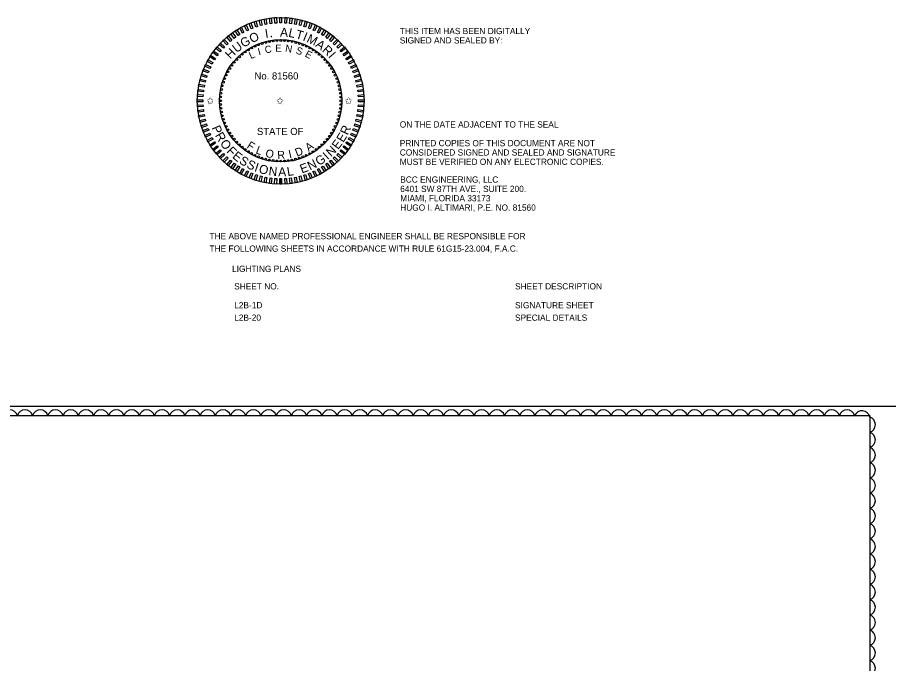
# Model space of a CAD drawing. Extents: x -816.9 to -790.1, y -2199.5 to -2184.5.
# Drawn here: x -804.97 to -795.17, y -2191.79 to -2184.53 of the extents above; entities that cross this region are included whole.
import ezdxf

# ---------------------------------------------------------------- set-up
doc = ezdxf.new("R2010")
doc.units = 0
for name, color, linetype in [('Cloud_dp', 7, 'Continuous'), ('Logo_dp', 7, 'Continuous'), ('NonPlottingEle_dp', 7, 'Continuous'), ('PlotBorder_dp', 7, 'Continuous'), ('SheetBorder_dp', 7, 'Continuous'), ('TextMisc', 7, 'Continuous'), ('TextNotes', 7, 'Continuous')]:
    doc.layers.add(name, color=color, linetype=linetype)

msp = doc.modelspace()

# ---------------------------------------------------------------- linework, layer by layer
at = {"layer": 'Cloud_dp'}
for centre, radius, start, end in [((-805.0532, -2189.0276), 0.0897, 17.5, 162.5), ((-804.882, -2189.0276), 0.0897, 17.5, 162.5), ((-804.7109, -2189.0276), 0.0897, 17.5, 162.5), ((-804.5398, -2189.0276), 0.0897, 17.5, 162.5), ((-804.3687, -2189.0276), 0.0897, 17.5, 162.5), ((-804.1976, -2189.0276), 0.0897, 17.5, 162.5), ((-804.0264, -2189.0276), 0.0897, 17.5, 162.5), ((-803.8553, -2189.0276), 0.0897, 17.5, 162.5), ((-803.6842, -2189.0276), 0.0897, 17.5, 162.5), ((-803.5131, -2189.0276), 0.0897, 17.5, 162.5), ((-803.3419, -2189.0276), 0.0897, 17.5, 162.5), ((-803.1708, -2189.0276), 0.0897, 17.5, 162.5), ((-802.9997, -2189.0276), 0.0897, 17.5, 162.5), ((-802.8286, -2189.0276), 0.0897, 17.5, 162.5), ((-802.6575, -2189.0276), 0.0897, 17.5, 162.5), ((-802.4863, -2189.0276), 0.0897, 17.5, 162.5), ((-802.3152, -2189.0276), 0.0897, 17.5, 162.5), ((-802.1441, -2189.0276), 0.0897, 17.5, 162.5), ((-801.973, -2189.0276), 0.0897, 17.5, 162.5), ((-801.8018, -2189.0276), 0.0897, 17.5, 162.5), ((-801.6307, -2189.0276), 0.0897, 17.5, 162.5), ((-801.4596, -2189.0276), 0.0897, 17.5, 162.5), ((-801.2885, -2189.0276), 0.0897, 17.5, 162.5), ((-801.1174, -2189.0276), 0.0897, 17.5, 162.5), ((-800.9462, -2189.0276), 0.0897, 17.5, 162.5), ((-800.7751, -2189.0276), 0.0897, 17.5, 162.5), ((-800.604, -2189.0276), 0.0897, 17.5, 162.5), ((-800.4329, -2189.0276), 0.0897, 17.5, 162.5), ((-800.2617, -2189.0276), 0.0897, 17.5, 162.5), ((-800.0906, -2189.0276), 0.0897, 17.5, 162.5), ((-799.9195, -2189.0276), 0.0897, 17.5, 162.5), ((-799.7484, -2189.0276), 0.0897, 17.5, 162.5), ((-799.5772, -2189.0276), 0.0897, 17.5, 162.5), ((-799.4061, -2189.0276), 0.0897, 17.5, 162.5), ((-799.235, -2189.0276), 0.0897, 17.5, 162.5), ((-799.0639, -2189.0276), 0.0897, 17.5, 162.5), ((-798.8928, -2189.0276), 0.0897, 17.5, 162.5), ((-798.7216, -2189.0276), 0.0897, 17.5, 162.5), ((-798.5505, -2189.0276), 0.0897, 17.5, 162.5), ((-798.3794, -2189.0276), 0.0897, 17.5, 162.5), ((-798.2083, -2189.0276), 0.0897, 17.5, 162.5), ((-798.0371, -2189.0276), 0.0897, 17.5, 162.5), ((-797.866, -2189.0276), 0.0897, 17.5, 162.5), ((-797.6949, -2189.0276), 0.0897, 17.5, 162.5), ((-797.5238, -2189.0276), 0.0897, 17.5, 162.5), ((-797.3527, -2189.0276), 0.0897, 17.5, 162.5), ((-797.1815, -2189.0276), 0.0897, 17.5, 162.5), ((-797.0104, -2189.0276), 0.0897, 17.5, 162.5), ((-796.8393, -2189.0276), 0.0897, 17.5, 162.5), ((-796.6682, -2189.0276), 0.0897, 17.5, 162.5), ((-796.497, -2189.0276), 0.0897, 17.5, 162.5), ((-796.3259, -2189.0276), 0.0897, 17.5, 162.5), ((-796.1548, -2189.0276), 0.0897, 17.5, 162.5), ((-795.9837, -2189.0276), 0.0897, 17.5, 162.5), ((-795.8126, -2189.0276), 0.0897, 17.5, 162.5), ((-795.6414, -2189.0276), 0.0897, 17.5, 162.5), ((-795.4735, -2189.036), 0.0896, 11.74536, 156.74536), ((-795.4127, -2189.1033), 0.0897, 287.5, 72.5), ((-795.4127, -2189.2745), 0.0897, 287.5, 72.5), ((-795.4127, -2189.4456), 0.0897, 287.5, 72.5), ((-795.4127, -2189.6167), 0.0897, 287.5, 72.5), ((-795.4127, -2189.7878), 0.0897, 287.5, 72.5), ((-795.4127, -2189.959), 0.0897, 287.5, 72.5), ((-795.4127, -2190.1301), 0.0897, 287.5, 72.5), ((-795.4127, -2190.3012), 0.0897, 287.5, 72.5), ((-795.4127, -2190.4723), 0.0897, 287.5, 72.5), ((-795.4127, -2190.6434), 0.0897, 287.5, 72.5), ((-795.4127, -2190.8146), 0.0897, 287.5, 72.5), ((-795.4127, -2190.9857), 0.0897, 287.5, 72.5), ((-795.4127, -2191.1568), 0.0897, 287.5, 72.5), ((-795.4127, -2191.3279), 0.0897, 287.5, 72.5), ((-795.4127, -2191.4991), 0.0897, 287.5, 72.5), ((-795.4127, -2191.6702), 0.0897, 287.5, 72.5), ((-795.4127, -2191.8413), 0.0897, 287.5, 72.5)]:
    msp.add_arc(centre, radius, start, end, dxfattribs=at)
at = {"layer": 'Logo_dp'}
for p, q in [((-802.0181, -2186.4002), (-802.0183, -2186.3377)), ((-802.0081, -2186.4002), (-802.0083, -2186.3377)), ((-801.9981, -2186.4001), (-801.9983, -2186.3377))]:
    msp.add_line(p, q, dxfattribs=at)
for points in [[(-802.1076, -2184.594), (-802.1277, -2184.5965), (-802.1355, -2184.5346), (-802.1155, -2184.5321)], [(-802.0529, -2184.5894), (-802.073, -2184.5907), (-802.0769, -2184.5284), (-802.0568, -2184.5271)], [(-801.9979, -2184.5884), (-802.0181, -2184.5884), (-802.0181, -2184.5259), (-801.9979, -2184.5259)], [(-801.943, -2184.5907), (-801.9632, -2184.5895), (-801.9592, -2184.5272), (-801.9391, -2184.5284)], [(-801.8884, -2184.5965), (-801.9084, -2184.594), (-801.9006, -2184.5321), (-801.8806, -2184.5346)], [(-802.3713, -2184.6673), (-802.3896, -2184.6759), (-802.4161, -2184.6194), (-802.3979, -2184.6108)], [(-802.3206, -2184.646), (-802.3394, -2184.6535), (-802.3624, -2184.5954), (-802.3436, -2184.588)], [(-802.2687, -2184.628), (-802.2879, -2184.6343), (-802.3072, -2184.5749), (-802.288, -2184.5687)], [(-802.2158, -2184.6133), (-802.2353, -2184.6183), (-802.2508, -2184.5579), (-802.2313, -2184.5528)], [(-802.162, -2184.6019), (-802.1818, -2184.6057), (-802.1935, -2184.5444), (-802.1737, -2184.5406)], [(-801.8342, -2184.6058), (-801.854, -2184.602), (-801.8423, -2184.5407), (-801.8225, -2184.5444)], [(-801.7807, -2184.6184), (-801.8003, -2184.6133), (-801.7847, -2184.5529), (-801.7652, -2184.5579)], [(-801.7281, -2184.6343), (-801.7473, -2184.6281), (-801.728, -2184.5687), (-801.7088, -2184.5749)], [(-801.6766, -2184.6535), (-801.6954, -2184.6461), (-801.6724, -2184.5881), (-801.6537, -2184.5955)], [(-801.6265, -2184.6759), (-801.6447, -2184.6673), (-801.6182, -2184.6109), (-801.5999, -2184.6195)], [(-802.514, -2184.7494), (-802.5303, -2184.7613), (-802.567, -2184.7108), (-802.5507, -2184.6989)], [(-802.4682, -2184.7191), (-802.4852, -2184.7299), (-802.5187, -2184.6772), (-802.5016, -2184.6664)], [(-802.4206, -2184.6916), (-802.4382, -2184.7014), (-802.4683, -2184.6467), (-802.4506, -2184.6369)], [(-801.5778, -2184.7014), (-801.5955, -2184.6917), (-801.5654, -2184.637), (-801.5477, -2184.6468)], [(-801.5308, -2184.73), (-801.5479, -2184.7192), (-801.5144, -2184.6665), (-801.4974, -2184.6773)], [(-801.4857, -2184.7614), (-801.5021, -2184.7495), (-801.4654, -2184.699), (-801.4491, -2184.7109)], [(-802.6388, -2184.8569), (-802.6526, -2184.8716), (-802.6981, -2184.8288), (-802.6843, -2184.8141)], [(-802.5994, -2184.8184), (-802.6142, -2184.8323), (-802.6569, -2184.7868), (-802.6422, -2184.7729)], [(-802.5578, -2184.7826), (-802.5734, -2184.7955), (-802.6131, -2184.7474), (-802.5976, -2184.7345)], [(-801.4427, -2184.7956), (-801.4583, -2184.7827), (-801.4185, -2184.7346), (-801.4029, -2184.7475)], [(-801.4019, -2184.8324), (-801.4166, -2184.8186), (-801.3739, -2184.7731), (-801.3592, -2184.7869)], [(-801.3635, -2184.8717), (-801.3773, -2184.857), (-801.3318, -2184.8143), (-801.318, -2184.829)], [(-802.7098, -2184.9407), (-802.7216, -2184.957), (-802.7721, -2184.9203), (-802.7602, -2184.904)], [(-802.6756, -2184.8976), (-802.6884, -2184.9132), (-802.7365, -2184.8734), (-802.7237, -2184.8579)], [(-801.3277, -2184.9133), (-801.3405, -2184.8978), (-801.2924, -2184.858), (-801.2796, -2184.8736)], [(-801.2945, -2184.9571), (-801.3064, -2184.9408), (-801.2559, -2184.9041), (-801.244, -2184.9205)], [(-802.7697, -2185.0327), (-802.7794, -2185.0504), (-802.8341, -2185.0203), (-802.8244, -2185.0027)], [(-802.7412, -2184.9858), (-802.752, -2185.0028), (-802.8047, -2184.9694), (-802.7939, -2184.9523)], [(-801.2641, -2185.003), (-801.2749, -2184.9859), (-801.2222, -2184.9525), (-801.2114, -2184.9695)], [(-801.2367, -2185.0506), (-801.2464, -2185.0329), (-801.1917, -2185.0028), (-801.182, -2185.0205)], [(-802.8176, -2185.1316), (-802.825, -2185.1503), (-802.8831, -2185.1274), (-802.8756, -2185.1086)], [(-802.7952, -2185.0814), (-802.8038, -2185.0997), (-802.8603, -2185.0731), (-802.8517, -2185.0548)], [(-801.2123, -2185.0998), (-801.2209, -2185.0816), (-801.1645, -2185.055), (-801.1559, -2185.0732)], [(-801.1911, -2185.1505), (-801.1985, -2185.1317), (-801.1405, -2185.1088), (-801.1331, -2185.1275)], [(-802.8368, -2185.1831), (-802.8431, -2185.2022), (-802.9024, -2185.183), (-802.8962, -2185.1638)], [(-801.1731, -2185.2024), (-801.1793, -2185.1832), (-801.12, -2185.1639), (-801.1137, -2185.1831)], [(-802.8654, -2185.2891), (-802.8692, -2185.309), (-802.9305, -2185.2973), (-802.9267, -2185.2774)], [(-802.8528, -2185.2356), (-802.8578, -2185.2552), (-802.9182, -2185.2397), (-802.9132, -2185.2201)], [(-801.1584, -2185.2554), (-801.1634, -2185.2358), (-801.1029, -2185.2203), (-801.0979, -2185.2398)], [(-801.147, -2185.3091), (-801.1508, -2185.2893), (-801.0895, -2185.2776), (-801.0857, -2185.2974)], [(-802.8804, -2185.3979), (-802.8817, -2185.4181), (-802.944, -2185.4142), (-802.9427, -2185.394)], [(-802.8746, -2185.3433), (-802.8771, -2185.3633), (-802.9391, -2185.3555), (-802.9365, -2185.3355)], [(-801.139, -2185.3635), (-801.1416, -2185.3435), (-801.0797, -2185.3357), (-801.0771, -2185.3557)], [(-801.1345, -2185.4183), (-801.1358, -2185.3981), (-801.0735, -2185.3942), (-801.0722, -2185.4144)], [(-802.8828, -2185.4529), (-802.8828, -2185.473), (-802.9452, -2185.473), (-802.9452, -2185.4529)], [(-802.8817, -2185.5078), (-802.8804, -2185.5279), (-802.9427, -2185.5318), (-802.944, -2185.5117)], [(-801.1358, -2185.5281), (-801.1345, -2185.508), (-801.0722, -2185.5119), (-801.0735, -2185.532)], [(-801.1334, -2185.4732), (-801.1334, -2185.453), (-801.071, -2185.453), (-801.071, -2185.4732)], [(-802.8772, -2185.5626), (-802.8746, -2185.5826), (-802.9366, -2185.5904), (-802.9391, -2185.5704)], [(-801.1416, -2185.5828), (-801.1391, -2185.5627), (-801.0771, -2185.5706), (-801.0797, -2185.5906)], [(-802.8692, -2185.6169), (-802.8654, -2185.6368), (-802.9267, -2185.6484), (-802.9305, -2185.6286)], [(-802.8578, -2185.6707), (-802.8528, -2185.6902), (-802.9133, -2185.7058), (-802.9183, -2185.6862)], [(-801.1634, -2185.6904), (-801.1584, -2185.6709), (-801.098, -2185.6864), (-801.103, -2185.7059)], [(-801.1508, -2185.6369), (-801.147, -2185.6171), (-801.0857, -2185.6288), (-801.0895, -2185.6486)], [(-802.8431, -2185.7236), (-802.8369, -2185.7428), (-802.8962, -2185.7621), (-802.9025, -2185.7429)], [(-802.8251, -2185.7756), (-802.8177, -2185.7943), (-802.8757, -2185.8173), (-802.8831, -2185.7985)], [(-801.1986, -2185.7945), (-801.1912, -2185.7757), (-801.1331, -2185.7987), (-801.1406, -2185.8175)], [(-801.1794, -2185.743), (-801.1731, -2185.7238), (-801.1138, -2185.7431), (-801.12, -2185.7623)], [(-802.8039, -2185.8262), (-802.7953, -2185.8445), (-802.8518, -2185.8711), (-802.8604, -2185.8528)], [(-802.7795, -2185.8755), (-802.7698, -2185.8932), (-802.8245, -2185.9232), (-802.8342, -2185.9056)], [(-801.2465, -2185.8933), (-801.2368, -2185.8757), (-801.1821, -2185.9057), (-801.1918, -2185.9234)], [(-801.221, -2185.8447), (-801.2124, -2185.8264), (-801.1559, -2185.853), (-801.1645, -2185.8712)], [(-802.7521, -2185.9231), (-802.7413, -2185.9401), (-802.794, -2185.9736), (-802.8048, -2185.9566)], [(-802.7217, -2185.9689), (-802.7099, -2185.9852), (-802.7604, -2186.0219), (-802.7722, -2186.0056)], [(-801.3065, -2185.9854), (-801.2946, -2185.9691), (-801.2441, -2186.0058), (-801.256, -2186.0221)], [(-801.275, -2185.9403), (-801.2642, -2185.9233), (-801.2115, -2185.9567), (-801.2223, -2185.9738)], [(-802.6886, -2186.0127), (-802.6757, -2186.0283), (-802.7238, -2186.0681), (-802.7366, -2186.0525)], [(-802.6527, -2186.0544), (-802.6389, -2186.0691), (-802.6844, -2186.1118), (-802.6982, -2186.0971)], [(-802.6143, -2186.0937), (-802.5996, -2186.1075), (-802.6423, -2186.153), (-802.657, -2186.1392)], [(-801.4168, -2186.1076), (-801.4021, -2186.0938), (-801.3593, -2186.1393), (-801.374, -2186.1531)], [(-801.3775, -2186.0692), (-801.3637, -2186.0545), (-801.3182, -2186.0972), (-801.332, -2186.1119)], [(-801.3406, -2186.0284), (-801.3278, -2186.0129), (-801.2797, -2186.0527), (-801.2926, -2186.0682)], [(-802.5735, -2186.1305), (-802.5579, -2186.1434), (-802.5977, -2186.1914), (-802.6133, -2186.1786)], [(-802.5305, -2186.1647), (-802.5141, -2186.1765), (-802.5508, -2186.227), (-802.5672, -2186.2152)], [(-802.4854, -2186.1961), (-802.4683, -2186.2069), (-802.5018, -2186.2596), (-802.5188, -2186.2488)], [(-801.548, -2186.207), (-801.531, -2186.1962), (-801.4975, -2186.2489), (-801.5146, -2186.2597)], [(-801.5022, -2186.1766), (-801.4859, -2186.1648), (-801.4492, -2186.2153), (-801.4655, -2186.2271)], [(-801.4584, -2186.1435), (-801.4429, -2186.1306), (-801.4031, -2186.1787), (-801.4186, -2186.1916)], [(-802.4384, -2186.2246), (-802.4207, -2186.2343), (-802.4508, -2186.289), (-802.4685, -2186.2793)], [(-802.3897, -2186.2501), (-802.3715, -2186.2587), (-802.3981, -2186.3152), (-802.4163, -2186.3066)], [(-802.3396, -2186.2725), (-802.3208, -2186.28), (-802.3438, -2186.338), (-802.3625, -2186.3306)], [(-802.2881, -2186.2918), (-802.2689, -2186.298), (-802.2882, -2186.3574), (-802.3074, -2186.3511)], [(-801.7475, -2186.298), (-801.7283, -2186.2918), (-801.709, -2186.3512), (-801.7282, -2186.3574)], [(-801.6956, -2186.28), (-801.6768, -2186.2726), (-801.6538, -2186.3306), (-801.6726, -2186.3381)], [(-801.6449, -2186.2588), (-801.6266, -2186.2502), (-801.6001, -2186.3067), (-801.6183, -2186.3153)], [(-801.5957, -2186.2344), (-801.578, -2186.2247), (-801.5479, -2186.2794), (-801.5656, -2186.2891)], [(-802.2355, -2186.3077), (-802.216, -2186.3127), (-802.2315, -2186.3732), (-802.251, -2186.3682)], [(-802.182, -2186.3203), (-802.1622, -2186.3241), (-802.1739, -2186.3854), (-802.1937, -2186.3816)], [(-802.1278, -2186.3295), (-802.1078, -2186.3321), (-802.1156, -2186.394), (-802.1357, -2186.3915)], [(-802.0732, -2186.3353), (-802.0531, -2186.3366), (-802.057, -2186.3989), (-802.0771, -2186.3976)], [(-802.0183, -2186.3377), (-801.9981, -2186.3377), (-801.9981, -2186.4001), (-802.0183, -2186.4001)], [(-801.9633, -2186.3366), (-801.9432, -2186.3354), (-801.9393, -2186.3977), (-801.9594, -2186.3989)], [(-801.9086, -2186.3321), (-801.8886, -2186.3296), (-801.8807, -2186.3915), (-801.9008, -2186.394)], [(-801.8542, -2186.3241), (-801.8344, -2186.3203), (-801.8227, -2186.3817), (-801.8425, -2186.3854)], [(-801.8004, -2186.3128), (-801.7809, -2186.3077), (-801.7654, -2186.3682), (-801.7849, -2186.3732)]]:
    msp.add_lwpolyline(points, close=True, dxfattribs=at)
for centre in [(-802.2569, -2184.8332), (-802.2168, -2184.8188), (-802.176, -2184.807), (-802.1344, -2184.7977), (-802.0924, -2184.7911), (-802.0501, -2184.7871), (-802.0075, -2184.7858), (-801.965, -2184.7872), (-801.9227, -2184.7912), (-801.8807, -2184.7979), (-801.8391, -2184.8073), (-801.7983, -2184.8192), (-801.7583, -2184.8336), (-802.4057, -2184.9148), (-802.3705, -2184.891), (-802.3339, -2184.8693), (-802.2959, -2184.85), (-801.7193, -2184.8505), (-801.6814, -2184.8699), (-801.6448, -2184.8916), (-801.6096, -2184.9155), (-802.5295, -2185.0309), (-802.5014, -2184.999), (-802.4713, -2184.969), (-802.4393, -2184.9409), (-801.576, -2184.9416), (-801.5441, -2184.9698), (-801.5141, -2184.9999), (-801.486, -2185.0318), (-802.5796, -2185.0997), (-802.5556, -2185.0645), (-801.4599, -2185.0654), (-801.436, -2185.1006), (-802.6375, -2185.2132), (-802.6206, -2185.1742), (-802.6013, -2185.1363), (-801.4144, -2185.1373), (-801.3951, -2185.1752), (-801.3783, -2185.2143), (-802.6639, -2185.2941), (-802.652, -2185.2532), (-801.3639, -2185.2543), (-801.352, -2185.2952), (-802.6839, -2185.4199), (-802.6799, -2185.3776), (-802.6732, -2185.3356), (-801.3428, -2185.3367), (-801.3362, -2185.3787), (-801.3322, -2185.4211), (-802.6853, -2185.4625), (-802.684, -2185.505), (-801.3323, -2185.5061), (-801.3309, -2185.4636), (-802.68, -2185.5473), (-802.6734, -2185.5894), (-801.343, -2185.5905), (-801.3363, -2185.5485), (-802.6642, -2185.6309), (-802.6523, -2185.6718), (-802.638, -2185.7118), (-801.3787, -2185.7128), (-801.3642, -2185.6728), (-801.3523, -2185.632), (-802.6211, -2185.7509), (-802.6018, -2185.7888), (-801.4149, -2185.7898), (-801.3956, -2185.7519), (-802.5802, -2185.8254), (-802.5563, -2185.8606), (-802.5303, -2185.8943), (-801.4867, -2185.8951), (-801.4606, -2185.8615), (-801.4366, -2185.8264), (-802.5021, -2185.9262), (-802.4721, -2185.9563), (-802.4402, -2185.9845), (-802.4066, -2186.0106), (-801.6105, -2186.0112), (-801.5769, -2185.9852), (-801.5449, -2185.9571), (-801.5148, -2185.927), (-802.3714, -2186.0345), (-802.3348, -2186.0562), (-802.297, -2186.0755), (-802.2579, -2186.0925), (-802.2179, -2186.1069), (-801.7994, -2186.1073), (-801.7593, -2186.0929), (-801.7203, -2186.076), (-801.6824, -2186.0567), (-801.6457, -2186.0351), (-802.1771, -2186.1188), (-802.1356, -2186.1281), (-802.0935, -2186.1348), (-802.0512, -2186.1389), (-802.0081, -2186.1403), (-801.9661, -2186.1389), (-801.9238, -2186.135), (-801.8818, -2186.1283), (-801.8402, -2186.1191)]:
    msp.add_circle(centre, 0.01, dxfattribs=at)
at = {"layer": 'NonPlottingEle_dp'}
for radius in [0.9371, 0.6872]:
    msp.add_circle((-802.0081, -2185.463), radius, dxfattribs=at)
at = {"layer": 'PlotBorder_dp'}
msp.add_lwpolyline([(-811.3358, -2199.5006), (-794.8358, -2199.5006), (-794.8358, -2188.9006), (-811.3358, -2188.9006)], close=True, dxfattribs=at)
at = {"layer": 'SheetBorder_dp'}
for p, q in [((-810.7858, -2189.0006), (-795.3858, -2189.0006)), ((-795.3858, -2189.0006), (-795.3858, -2199.4006))]:
    msp.add_line(p, q, dxfattribs=at)

# ---------------------------------------------------------------- texts
at = {"layer": 'Logo_dp'}
for s, rotation, p in [('L', 23.30524, (-802.3439, -2184.9956)), ('I', 14.81888, (-802.2533, -2184.9528)), ('C', 8.98261, (-802.1808, -2184.9301)), ('E', 359.96623, (-802.0681, -2184.9112)), ('N', 350.64643, (-801.9613, -2184.9098)), ('S', 341.03996, (-801.8442, -2184.9286)), ('E', 331.16864, (-801.7428, -2184.9611))]:
    msp.add_text(s, height=0.08, rotation=rotation, dxfattribs=at).set_placement(p)
for p in [(-802.8427, -2185.501), (-802.0583, -2185.501), (-801.2868, -2185.501)]:
    msp.add_text('✩', height=0.08, dxfattribs=at).set_placement(p)
at = {"layer": 'TextMisc'}
for s, height, rotation, p in [('O', 0.1, 23.30524, (-802.3352, -2184.8165)), ('I', 0.1, 8.98261, (-802.177, -2184.7591)), ('A', 0.1, 356.89262, (-802.0166, -2184.7403)), ('L', 0.1, 347.47515, (-801.9271, -2184.7422)), ('T', 0.1, 344.27273, (-801.8472, -2184.7589)), ('I', 0.1, 337.77772, (-801.7672, -2184.7817)), ('M', 0.1, 334.48695, (-801.724, -2184.7985)), ('U', 0.1, 36.72494, (-802.5049, -2184.9286)), ('G', 0.1, 28.78207, (-802.4288, -2184.8681)), ('.', 0.1, 6.01169, (-802.1308, -2184.7504)), ('A', 0.1, 324.45371, (-801.6249, -2184.848)), ('H', 0.1, 44.34211, (-802.5748, -2185.0005)), ('R', 0.1, 317.64216, (-801.5485, -2184.902)), ('I', 0.1, 310.74416, (-801.4788, -2184.9659)), ('P', 0.1, 293.19548, (-802.7866, -2185.7657)), ('R', 0.1, 65.28865, (-801.2551, -2185.855)), ('R', 0.1, 300.25949, (-802.7497, -2185.8516)), ('O', 0.1, 307.26617, (-802.6956, -2185.9434)), ('E', 0.1, 53.99864, (-801.3615, -2186.0176)), ('E', 0.1, 58.61694, (-801.3043, -2185.9389)), ('F', 0.1, 314.20329, (-802.6222, -2186.0358)), ('F', 0.09, 328.53399, (-802.3964, -2185.9885)), ('L', 0.09, 339.48752, (-802.2953, -2186.0515)), ('D', 0.09, 22.22228, (-801.8255, -2186.0922)), ('A', 0.09, 35.54629, (-801.6939, -2186.0378)), ('N', 0.1, 44.34211, (-801.4415, -2186.0975)), ('E', 0.1, 321.0594, (-802.5589, -2186.0993)), ('S', 0.1, 327.82385, (-802.4827, -2186.1599)), ('O', 0.09, 348.08156, (-802.1858, -2186.092)), ('R', 0.09, 3.10738, (-802.0438, -2186.1182)), ('I', 0.09, 12.52485, (-801.9096, -2186.1091)), ('G', 0.1, 34.11362, (-801.5769, -2186.1977)), ('I', 0.1, 41.83906, (-801.4809, -2186.1317)), ('S', 0.1, 334.48695, (-802.3996, -2186.2112)), ('I', 0.1, 341.03996, (-802.311, -2186.2525)), ('O', 0.1, 344.27273, (-802.2619, -2186.2701)), ('E', 0.1, 20.51248, (-801.7696, -2186.2811)), ('N', 0.1, 26.0618, (-801.6781, -2186.2478)), ('N', 0.1, 353.78581, (-802.1476, -2186.3)), ('A', 0.1, 359.96623, (-802.0353, -2186.311)), ('L', 0.1, 8.98261, (-801.9297, -2186.3101))]:
    msp.add_text(s, height=height, rotation=rotation, dxfattribs=at).set_placement(p)
for s, height, p in [('THIS ITEM HAS BEEN DIGITALLY', 0.07, (-800.6693, -2184.7137)), ('SIGNED AND SEALED BY:', 0.07, (-800.6693, -2184.8187)), ('No. 81560', 0.07997, (-802.3027, -2185.2236)), ('ON THE DATE ADJACENT TO THE SEAL', 0.07, (-800.6693, -2185.7637)), ('STATE OF', 0.07997, (-802.275, -2185.8475)), ('PRINTED COPIES OF THIS DOCUMENT ARE NOT ', 0.07, (-800.6693, -2185.9737)), ('CONSIDERED SIGNED AND SEALED AND SIGNATURE ', 0.07, (-800.6693, -2186.0787)), ('MUST BE VERIFIED ON ANY ELECTRONIC COPIES.', 0.07, (-800.6693, -2186.1837)), ('BCC ENGINEERING, LLC', 0.07, (-800.6643, -2186.3835)), ('6401 SW 87TH AVE., SUITE 200.', 0.07, (-800.6643, -2186.4885)), ('MIAMI, FLORIDA 33173', 0.07, (-800.6643, -2186.5935)), ('HUGO I. ALTIMARI, P.E. NO. 81560', 0.07, (-800.6643, -2186.6985)), ('THE ABOVE NAMED PROFESSIONAL ENGINEER SHALL BE RESPONSIBLE FOR ', 0.07, (-802.8084, -2187.0197)), ('THE FOLLOWING SHEETS IN ACCORDANCE WITH RULE 61G15-23.004, F.A.C.', 0.07, (-802.8084, -2187.1597)), ('LIGHTING PLANS', 0.07, (-802.5547, -2187.3867))]:
    msp.add_text(s, height=height, dxfattribs=at).set_placement(p)
at = {"layer": 'TextNotes'}
for s, p in [('SHEET NO.', (-802.5312, -2187.5837)), ('SHEET DESCRIPTION', (-799.3737, -2187.5837)), ('L2B-1D', (-802.5312, -2187.796)), ('SIGNATURE SHEET', (-799.3737, -2187.7959)), ('L2B-20', (-802.5312, -2187.936)), ('SPECIAL DETAILS', (-799.3737, -2187.9359))]:
    msp.add_text(s, height=0.07, dxfattribs=at).set_placement(p)

doc.saveas('drawing.dxf')
